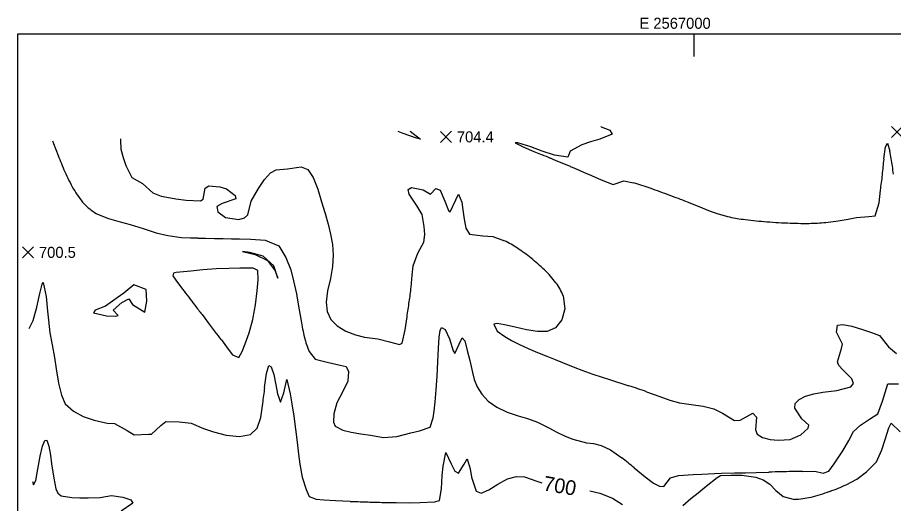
# Model space of a CAD drawing. Extents: x 2566079 to 2571326, y 424054 to 426896.
# Drawn here: x 2566079 to 2567271, y 426236 to 426896 of the extents above; entities that cross this region are included whole.
import ezdxf

# ---------------------------------------------------------------- set-up
doc = ezdxf.new("R2010")
doc.units = 0
for name, color, linetype in [('Contour_ADS_Label_Major', 7, 'Continuous'), ('Contour_ADS_Major', 7, 'Continuous'), ('Contour_ADS_Minor', 7, 'Continuous'), ('Contour_ADS_Spot_Elevation', 7, 'Continuous'), ('Contour_ADS_State_Plane_Border', 7, 'Continuous')]:
    doc.layers.add(name, color=color, linetype=linetype)

# ---------------------------------------------------------------- blocks, each defined once
blk = doc.blocks.new('S750')
at = {"layer": 'Contour_ADS_Spot_Elevation'}
for p, q in [((-0.5, 0.498), (0.5, -0.498)), ((-0.498, -0.5), (0.498, 0.5))]:
    blk.add_line(p, q, dxfattribs=at)

msp = doc.modelspace()

# ---------------------------------------------------------------- linework, layer by layer
at = {"layer": 'Contour_ADS_Major'}
for points in [[(2566095.4, 426473.6), (2566100.5, 426484.7), (2566105.4, 426502.8), (2566109.6, 426521.4), (2566113, 426533.9), (2566114.4, 426536.5), (2566118.5, 426517.1), (2566120.2, 426497.4), (2566121.3, 426485.2), (2566123.3, 426468), (2566126.6, 426451.5), (2566129.6, 426434.3), (2566131.7, 426418.9), (2566135.2, 426399.4), (2566139.4, 426383), (2566144.2, 426371.6), (2566155.5, 426361.3), (2566168.8, 426354), (2566183.5, 426349.1), (2566201.4, 426345.2), (2566211.4, 426344.7), (2566228.5, 426335), (2566238, 426329.2), (2566257.6, 426330), (2566261.5, 426330), (2566274.2, 426341.8), (2566281.2, 426347.3), (2566299.1, 426347.1), (2566315.4, 426345.2), (2566332.4, 426337.9), (2566345.8, 426333.2), (2566363.1, 426328.9), (2566381.2, 426327.1), (2566396.3, 426329.8), (2566405.6, 426338.5), (2566410.4, 426352.9), (2566413, 426371.8)], [(2566415.5, 426393.4), (2566418.3, 426412.6), (2566421.4, 426423.4), (2566424.7, 426421.7), (2566428.1, 426411.2), (2566431, 426397.3), (2566433.3, 426384.8), (2566437, 426373.7), (2566441.5, 426386.5), (2566445.8, 426404.4), (2566450.5, 426385.2), (2566452.7, 426371.3), (2566455.2, 426354.6), (2566457.7, 426336.8), (2566459.9, 426319.3), (2566461.8, 426303.2), (2566463.5, 426289.6), (2566466.6, 426271.7), (2566472, 426254.8), (2566476.3, 426245.6), (2566485.6, 426242), (2566496.1, 426240.9), (2566512.1, 426239.8), (2566532, 426238.9)], [(2567207.1, 426261.5), (2567221.6, 426269), (2567234.6, 426279.1), (2567248.2, 426292.4), (2567255.4, 426308.8), (2567260.2, 426322.9), (2567265.1, 426338.9), (2567268.3, 426345.3), (2567280.6, 426333.4)], [(2566574.9, 426237.5), (2566594.7, 426237.1), (2566612.3, 426237), (2566627.1, 426237.2), (2566646.7, 426238.1), (2566653.7, 426239.8), (2566656.4, 426256.1), (2566657.2, 426274.1), (2566658.4, 426286.7), (2566662, 426305.1), (2566669.2, 426289.9), (2566674.4, 426279.7), (2566679.6, 426277.1), (2566687, 426289.2), (2566691.3, 426296.8), (2566695.2, 426283.1), (2566697.3, 426271.8), (2566703.6, 426252.8), (2566710.2, 426250.2), (2566720.5, 426254.5), (2566733, 426262.4), (2566746.1, 426269.6), (2566758.3, 426272.5), (2566769.2, 426272), (2566786.2, 426266.3), (2566792.6, 426264.2)], [(2566984.6, 426233), (2566995.4, 426242.7), (2567005.5, 426250.6), (2567016.6, 426259.4), (2567031.3, 426271.3), (2567035.9, 426274.1), (2567049.8, 426274.5), (2567064.8, 426274.4), (2567083.9, 426271.8), (2567094, 426268.2), (2567103.2, 426262.1), (2567111.3, 426253.5), (2567121.2, 426245.4), (2567136.4, 426241.6)], [(2566858.3, 426253), (2566871.9, 426249.8), (2566888.8, 426243), (2566902.6, 426234.5)]]:
    msp.add_lwpolyline(points, dxfattribs=at)
for centre, radius, start, end in [((2567139.3, 426304.8), 729.2, 173.0232, 173.8774), ((2565594.5, 426471.2), 824.6, 353.0782, 353.8343), ((2567107.3, 426460.9), 222.3, 283.4742, 290.3755), ((2567101.1, 426492), 253.7, 289.2457, 294.6925), ((2567133.8, 426345.2), 103.6, 271.4604, 284.1488), ((2566627.3, 428547.1), 2310.2, 267.6365, 268.1723), ((2566632.8, 428706.4), 2469.6, 268.163, 268.6562)]:
    msp.add_arc(centre, radius, start, end, dxfattribs=at)
at = {"layer": 'Contour_ADS_Minor'}
for points in [[(2566613.6, 426742), (2566627.8, 426731), (2566622.2, 426732.3), (2566604, 426739), (2566597.1, 426741.5)], [(2566872.9, 426749), (2566873.4, 426748.1), (2566885.4, 426743.3), (2566888.3, 426737.8), (2566871.5, 426731), (2566859.2, 426727.3), (2566847.2, 426723.5), (2566831.2, 426715), (2566828.4, 426706.7), (2566810, 426709.3), (2566793.1, 426715), (2566777.7, 426720.5), (2566760.3, 426726.2), (2566756.3, 426726.1), (2566768.2, 426720.2), (2566781.8, 426714.6), (2566793.2, 426709.8)], [(2566126.9, 426728.9), (2566128.2, 426725.3), (2566134.5, 426708.9)], [(2566219.6, 426731.4), (2566219.3, 426729.8), (2566220.1, 426717.4), (2566222.9, 426706.1), (2566226.5, 426695.5), (2566234.7, 426679.2), (2566249.5, 426671), (2566263.4, 426658.3), (2566274.8, 426653.8), (2566282.5, 426652.4), (2566294.8, 426650.2), (2566308.8, 426648.1), (2566328.3, 426647.5), (2566331.8, 426649.4), (2566334.6, 426664.7), (2566339.7, 426667.5), (2566354.8, 426666.4), (2566363.5, 426663.7), (2566375.6, 426654.4), (2566376.2, 426650), (2566358, 426643.8), (2566350.4, 426639.6), (2566351.8, 426632.6), (2566362.4, 426624.9), (2566380.5, 426622.1), (2566388.3, 426624), (2566392.8, 426628.4), (2566397.4, 426646.9), (2566407.3, 426664.2), (2566415.4, 426676.2), (2566423.7, 426685.5), (2566431.3, 426689.6), (2566446.6, 426690.6), (2566465.3, 426693.6), (2566474.3, 426690), (2566481.7, 426679.1), (2566487.9, 426663.3), (2566493.1, 426646.1), (2566497.8, 426630.2), (2566501.9, 426615.8), (2566505.3, 426601.9), (2566507.8, 426588), (2566509, 426573.6), (2566508.1, 426558.2), (2566505, 426541.6), (2566501.3, 426525), (2566499.2, 426509.6), (2566500.5, 426496.7), (2566505.5, 426486.1), (2566514.1, 426477.4), (2566526, 426470.4), (2566539.3, 426465.2), (2566551.7, 426461.9), (2566569.5, 426459.7), (2566585.3, 426455.9), (2566599.3, 426452), (2566602.9, 426453.8), (2566606.7, 426471.8), (2566609.4, 426489.5)], [(2567258, 426704.2), (2567260.5, 426720.8), (2567263.3, 426725.8), (2567266.5, 426715)], [(2566856.2, 426683.4), (2566873.4, 426676), (2566889.8, 426669.4), (2566904.4, 426674.6), (2566917.7, 426671.7)], [(2566614.9, 426530.2), (2566616.4, 426546.5), (2566617.8, 426559), (2566624.1, 426576), (2566632.3, 426591), (2566633.5, 426601.4), (2566632.9, 426612.5), (2566629.8, 426628.9), (2566623.2, 426640.1), (2566612.4, 426656.6), (2566611.1, 426662.9), (2566615.6, 426665.4), (2566631.5, 426662.4), (2566641.5, 426656.5), (2566648.6, 426664.3), (2566654.5, 426662), (2566660.9, 426646.8), (2566666, 426634.1), (2566668, 426632.4), (2566676, 426648.6), (2566679.6, 426656.6), (2566684, 426645.4), (2566685.4, 426634.9), (2566686.9, 426622.3), (2566689.4, 426610.3), (2566694.2, 426602), (2566712.5, 426599.8), (2566726, 426598.8), (2566741.9, 426593.1)], [(2567179.2, 426617.9), (2567196.2, 426620.1), (2567209.5, 426622.5), (2567220.8, 426624.5), (2567237.6, 426625.9), (2567246.6, 426626.9), (2567251.7, 426644.6), (2567253.8, 426661.8)], [(2566990.4, 426645.8), (2567005.5, 426640), (2567021.9, 426633.4), (2567031.4, 426629.9), (2567045.6, 426626)], [(2566186.1, 426630.3), (2566203, 426623.1), (2566218.9, 426618.7), (2566232.4, 426615.1), (2566250.3, 426609.7), (2566268, 426603.7), (2566283.9, 426600.2), (2566302.4, 426597.4), (2566314.7, 426597.1)], [(2566324.9, 426596.8), (2566335.1, 426596.6), (2566347.2, 426596.3), (2566359.3, 426596), (2566370.4, 426595.8), (2566381.4, 426595.5), (2566396.8, 426595.1), (2566416.4, 426594), (2566434.7, 426586.1), (2566444.5, 426570.2), (2566451.2, 426553.7), (2566454.9, 426538.8), (2566458.8, 426521.1), (2566461.9, 426504), (2566465.1, 426484.4)], [(2566403.3, 426506.1), (2566405.6, 426525), (2566406.8, 426539.9), (2566406.2, 426552.8), (2566400.1, 426555.7), (2566382, 426555.9), (2566367, 426555.5), (2566349.8, 426554.7), (2566331.7, 426553.4), (2566315.1, 426551.9), (2566295.3, 426550), (2566291.6, 426549.1), (2566290.6, 426545.6), (2566294.6, 426539.6), (2566303.9, 426527.2)], [(2566822, 426518.1), (2566824.3, 426500.7), (2566820.1, 426485.6), (2566811.5, 426474.9), (2566800.1, 426469.9), (2566786.8, 426469.5), (2566771.9, 426471.9), (2566756.3, 426475.4), (2566742.2, 426478.7), (2566732.1, 426480.5), (2566727.6, 426479.8), (2566732.1, 426470), (2566742.4, 426462.8), (2566751.5, 426457.7), (2566762.3, 426452.2), (2566774.4, 426446.6), (2566787, 426441.2), (2566799.4, 426436.1), (2566810.8, 426431.5), (2566821.1, 426427.4), (2566837.6, 426420.6), (2566847.2, 426417), (2566862.3, 426411.8), (2566885, 426404.5), (2566911.2, 426396)], [(2566330.4, 426492.7), (2566340.1, 426479.9), (2566348.5, 426469)], [(2566384.8, 426442.4), (2566389.1, 426453.1), (2566394.5, 426468.1), (2566399.5, 426486.2)], [(2566935.3, 426387.8), (2566953.2, 426381.2), (2566966.9, 426376.2), (2566980.3, 426372.8), (2566995.9, 426370.5), (2567012.2, 426368.2), (2567027, 426364.5), (2567038.5, 426358.6), (2567055.1, 426348.7), (2567062.7, 426349.3), (2567079.8, 426358.8), (2567084.8, 426353.5), (2567083.5, 426336.1), (2567085.8, 426330), (2567093, 426325.6), (2567103.3, 426323), (2567114.2, 426321.9), (2567130.7, 426322.8), (2567145.4, 426329.5), (2567155.4, 426338.3), (2567156, 426342.3), (2567146.8, 426351.1), (2567136.9, 426365.3), (2567137.7, 426371.8), (2567142.8, 426377.4), (2567151.6, 426381.9), (2567163.1, 426385.1), (2567175, 426387.2), (2567194.4, 426389.7), (2567213.1, 426394.7), (2567217, 426399.1), (2567214.6, 426405.4), (2567202.4, 426417.4), (2567197.1, 426423.5), (2567195.2, 426428.6), (2567200.8, 426446.4), (2567201.8, 426452.7), (2567193.6, 426468.8), (2567195, 426478.2), (2567202.2, 426479.3), (2567214.7, 426476.9), (2567229.2, 426472.6), (2567241.6, 426468.4), (2567252.1, 426464.2), (2567264.4, 426449.1), (2567275.4, 426439.8)], [(2566476.3, 426442.6), (2566484.5, 426432.2), (2566500.6, 426428.2), (2566518.4, 426424), (2566526.6, 426422.3), (2566529.8, 426415.5), (2566528.6, 426402.3), (2566522, 426388.1), (2566513.9, 426372.6), (2566509.8, 426357.7), (2566509.3, 426346.5), (2566511.7, 426341.1), (2566522.1, 426335.5), (2566533.3, 426333), (2566546.6, 426330.7), (2566559.5, 426328.7), (2566577.5, 426325.8), (2566595.6, 426327), (2566614.7, 426331.9), (2566626.2, 426334.9), (2566641, 426339.5), (2566645.1, 426352.5), (2566646.1, 426361.4), (2566647.6, 426374.3), (2566649.2, 426390.6), (2566650.5, 426409.1), (2566651.5, 426428.7), (2566652.3, 426447.1), (2566653.2, 426461.8), (2566654.5, 426470.9), (2566656.4, 426475), (2566661.3, 426472.3), (2566667, 426459.8), (2566672.2, 426443.6), (2566674.5, 426439.7), (2566680.5, 426452.7), (2566684.4, 426461.1), (2566688, 426457.2), (2566691.2, 426443.8), (2566694.7, 426430.3), (2566698.3, 426414.1), (2566700.8, 426404.4), (2566704.9, 426394.3), (2566711, 426384.4), (2566719.7, 426375.1), (2566731.4, 426366.9), (2566745.8, 426360.2), (2566760.7, 426355.1), (2566773.1, 426351.4), (2566786.9, 426346.7), (2566802.3, 426338.8), (2566813.3, 426333), (2566824.7, 426327.6), (2566835.1, 426323.3), (2566853.8, 426318.5), (2566863, 426317.4), (2566873.5, 426314.9), (2566886.2, 426308.9), (2566901.8, 426297.9)], [(2566356.8, 426458.2), (2566366.1, 426445.9), (2566371.8, 426438.1), (2566380.3, 426434.2), (2566384.8, 426442.4), (2566384.8, 426442.4)], [(2567147.6, 426279.6), (2567164.3, 426279.8), (2567175.7, 426277.2), (2567183.4, 426279.7), (2567190.8, 426289.7), (2567196.1, 426297.9), (2567202.2, 426307.6), (2567210.6, 426321.7), (2567217, 426334), (2567226.3, 426342.4), (2567238.7, 426350.6), (2567250.1, 426357.9), (2567256.2, 426374.9), (2567262, 426392.9), (2567263.6, 426398.7), (2567278.2, 426398.7)], [(2566099.5, 426265.7), (2566101.1, 426261.5), (2566104.1, 426267.4), (2566107, 426282.6), (2566110, 426300.2), (2566113.2, 426314), (2566116.4, 426321.7), (2566119.4, 426321.8), (2566121.9, 426313.9), (2566124, 426301.7), (2566125.7, 426289.8), (2566128.8, 426270.5), (2566131.6, 426256.1), (2566134.4, 426249.9), (2566138.6, 426246.2), (2566153.3, 426244), (2566164.1, 426243.7), (2566175.5, 426243.6), (2566191.9, 426244.3), (2566207, 426246.8), (2566222.8, 426244.5), (2566233.4, 426240.8), (2566236.3, 426236.2), (2566220.2, 426225.7)], [(2566918.3, 426284.5), (2566933.4, 426272.2), (2566944.9, 426263.8), (2566953.1, 426259.5), (2566958.6, 426259.1), (2566967.9, 426270.7), (2566978.8, 426274.2), (2566998.7, 426275.2), (2567010.3, 426275.9), (2567027.7, 426276.8), (2567037.2, 426277), (2567055, 426277.4)], [(2567069.8, 426277.8), (2567084.5, 426278.1), (2567101.6, 426278.5)]]:
    msp.add_lwpolyline(points, dxfattribs=at)
for points in [[(2566433.5, 426542.2), (2566428, 426559.2), (2566413.6, 426572.3), (2566395.6, 426577.2), (2566385.4, 426578.3), (2566402.5, 426574.2), (2566419.5, 426566.4), (2566429.9, 426552.1), (2566433.5, 426542.2)], [(2566198.9, 426504.2), (2566185, 426498.8), (2566182.8, 426494.9), (2566200.5, 426491), (2566213, 426490.6), (2566216.2, 426491.3), (2566209.5, 426498.7), (2566221.3, 426509), (2566231, 426514.3), (2566236, 426506.2), (2566252.8, 426496.2), (2566255.3, 426510.8), (2566254.3, 426526.7), (2566237.4, 426533), (2566223.9, 426522), (2566215.1, 426515.4), (2566198.9, 426504.2)]]:
    msp.add_lwpolyline(points, close=True, dxfattribs=at)
for centre, radius, start, end in [((2566645.3, 426908.6), 548.4, 201.355, 203.8402), ((2560814.1, 412326.1), 15576.9, 67.38245, 67.42783), ((2562479.7, 416318.7), 11250.9, 67.24388, 67.39285), ((2566753.7, 426621.8), 521.2, 8.0109, 10.298), ((2564910, 422117.3), 4963.5, 66.9143, 67.223), ((2573117.3, 426100.8), 5890.3, 174.12068, 174.33244), ((2566360.1, 426564.5), 919, 7.4558, 8.1317), ((2566378.5, 426790.6), 256.7, 203.8181, 209.7011), ((2578565.3, 425552.9), 11365.8, 174.29602, 174.34851), ((2566774.6, 426195.2), 497.6, 70.5444, 73.2859), ((2566380.5, 426754.6), 878.2, 353.933, 354.613), ((2566263.7, 426725.3), 124.6, 209.7822, 221.142), ((2566481.6, 425359.2), 1383.4, 69.4618, 70.6343), ((2566112.5, 424362.9), 2445.9, 68.9657, 69.5531), ((2566226.1, 426697.2), 77.9, 223.7929, 239.154), ((2567105.2, 426898.1), 278.6, 257.6623, 262.041), ((2567136.3, 427133.3), 515.7, 262.2259, 265.4155), ((2567153.2, 427288.5), 671.8, 265.0431, 267.7616), ((2567150.6, 427142.5), 525.8, 267.4216, 270.6357), ((2567151.4, 426933), 316.3, 270.913, 275.0546), ((2566640.3, 439712.4), 13119.3, 268.57774, 268.62244), ((2566675.2, 426456.6), 151.9, 56.2434, 63.9246), ((2566628.3, 426383.8), 238.5, 51.0863, 56.6097), ((2566633.6, 426384.9), 234.3, 45.9853, 51.9269), ((2566696.9, 426448.6), 144.5, 37.2072, 46.4717), ((2574050.2, 432429), 9738.3, 217.30321, 217.46455), ((2565813.1, 426621.1), 807, 352.103, 353.5342), ((2566752.4, 426491.2), 74.6, 21.0904, 36.9103), ((2579517.6, 436612.7), 16622.8, 217.44751, 217.50297), ((2566133.1, 426546.8), 273.2, 347.1833, 351.4206), ((2563854.3, 426902.8), 2785.9, 351.4688, 351.8997), ((2566797.3, 426541.7), 337.1, 189.7819, 193.7285), ((2562703.4, 423664.6), 4599.1, 37.4042, 37.5747), ((2566579.5, 426488.4), 112.9, 193.6762, 203.9132), ((2566489.2, 425108.9), 1354.5, 70.7707, 71.8465), ((2565910.2, 425053.6), 1591.1, 50.6837, 51.4499), ((2566570.6, 446427.9), 20156.3, 271.37716, 271.4191), ((2567492.6, 410364.6), 15918.8, 91.346, 91.40743), ((2567339.6, 416914.8), 9366.8, 91.17414, 91.35176)]:
    msp.add_arc(centre, radius, start, end, dxfattribs=at)
at = {"layer": 'Contour_ADS_State_Plane_Border'}
msp.add_line((2567000, 426843.7), (2567000, 426873.7), dxfattribs=at)
msp.add_lwpolyline([(2566079.3, 424077.1), (2571302.9, 424077.1), (2571302.9, 426873.7), (2566079.3, 426873.7), (2566079.3, 424077.1)], close=True, dxfattribs=at)

# ---------------------------------------------------------------- block references
at = {"layer": 'Contour_ADS_Spot_Elevation', "xscale": 15, "yscale": 15}
for p in [(2566662.2, 426734.3), (2567276.3, 426740.8), (2566093.5, 426577.3)]:
    msp.add_blockref('S750', p, dxfattribs=at)

# ---------------------------------------------------------------- texts
at = {"layer": 'Contour_ADS_Label_Major'}
msp.add_text('700', height=20, rotation=350.3289, dxfattribs=at).set_placement((2566793.7, 426253.9))
at = {"layer": 'Contour_ADS_Spot_Elevation'}
for s, p in [('704.4', (2566677.2, 426726.8)), ('700.5', (2566108.5, 426569.8))]:
    msp.add_text(s, height=15, dxfattribs=at).set_placement(p)
at = {"layer": 'Contour_ADS_State_Plane_Border'}
msp.add_text(' E 2567000', height=15, dxfattribs=at).set_placement((2566920, 426881.2))

doc.saveas('drawing.dxf')
